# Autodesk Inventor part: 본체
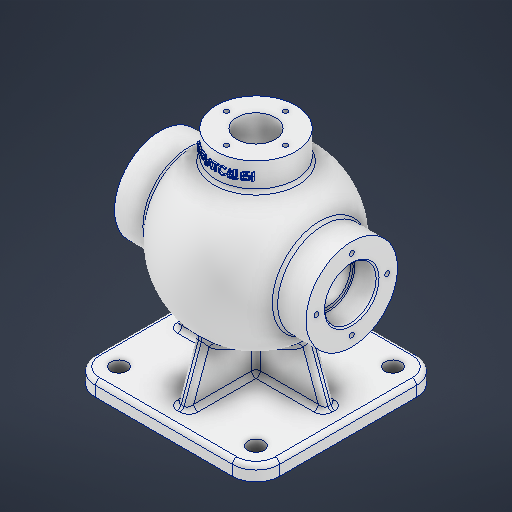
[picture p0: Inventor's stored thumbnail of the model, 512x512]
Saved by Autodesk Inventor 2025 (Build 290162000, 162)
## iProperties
Created: 2025-08
Part Number: 본체
Material: 알루미늄 6061
Document SubType Name: Modeling
Designer: infra005
Density: 2.7 g/cm^3
Appearance: 알루미늄 - 평지
Mass: 1527.05 g
Surface Area: 1174.47 cm^2
Volume: 565.574 cm^3
Author: infra005
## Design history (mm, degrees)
sketch "스케치1"
  geometry: L1 (46.5, 62.5)-(-46.5, 62.5); L2 (-62.5, 46.5)-(-62.5, -46.5); L3 (-46.5, -62.5)-(46.5, -62.5); L4 (62.5, -46.5)-(62.5, 46.5); L5 (62.5, 62.5)-(-62.5, -62.5); L6 (-62.5, 62.5)-(62.5, -62.5); L7 (0, -92.139)-(0, 92.139) reference; A1 r 16 centre (46.5, -46.5) between (46.5, -62.5) and (62.5, -46.5); A2 r 16 centre (-46.5, -46.5) between (-62.5, -46.5) and (-46.5, -62.5); A3 r 16 centre (-46.5, 46.5) between (-46.5, 62.5) and (-62.5, 46.5); A4 r 16 centre (46.5, 46.5) between (62.5, 46.5) and (46.5, 62.5); 1 further point
  constraints: 12 end point, 8 point on circle, 8 point on line, 8 tangent, 4 centre point, 3 equal radius, 2 midpoint, 2 parallel, 1 horizontal, 1 perpendicular
  dimensions: "d0" = 125 distance of L5.end L6.end; "d1" = 125 distance of L6.start L5.end; "d2" = 16 radius of A1
extrude "돌출1" new body sketch "스케치1" distance "d5" = 10; taper "d6" = 0 deg
sketch "스케치3"
  geometry: L1 (0, 159.709)-(0, -26.618) reference; L2 (-79.159, 85)-(102.785, 85); L3 (-115.548, 0)-(139.174, 0) reference; A1 r 54 centre (0, 85) between (0, 139) and (0, 31); 1 further point
  constraints: 4 point on line, 2 end point, 2 point on circle, 1 centre point, 1 horizontal
  dimensions: "d9" = 108 diameter of A1; "d10" = 85 distance between parallel lines of L3 L2
revolve "회전1" sketch "스케치3" stored, may be unused: angle "d11" = 90 deg
sketch "스케치4"
  geometry: L1 (-65, 116)-(0, 116); L2 (0, 116)-(0, 54); L3 (-65, 85)-(-65, 116); L4 (-153.218, 85)-(119.438, 85); L5 (-207.749, 0)-(173.969, 0) reference; L6 (0, 166.8)-(0, -27.8) reference; L7 (-65, 85)-(0, 85); 2 further points
  constraints: 10 end point, 4 point on line, 2 horizontal, 1 parallel, 1 perpendicular
  dimensions: "d13" = 85 distance between parallel lines of L5 L4; "d14" = 31 distance between parallel lines of L4 L1; "d15" = 65 distance of L1.start L1.end
revolve "회전2" sketch "스케치4" stored, may be unused: angle "d16" = 90 deg
node "작업 평면1"
sketch "스케치5"
  geometry: C1 r 27 at (0, 0); 1 further point
  constraints: 1 centre point, 1 coincident
  dimensions: "d18" = 54 diameter of C1
extrude "돌출2" join sketch "스케치5" stored distance "d19" = 10; taper "d20" = 0 deg
sketch "스케치7"
  geometry: L1 (0, 57.838)-(-33.088, 57.838); L2 (-33.088, 57.838)-(-50.5, 10); L3 (-50.5, 10)-(0, 10); L4 (0, 10)-(0, 57.838); L5 (-46.5, 10)-(-62.5, 10) reference; L6 (-62.5, 0)-(-62.5, 10) reference; 2 further points
  constraints: 8 end point, 1 horizontal, 1 midpoint, 1 parallel, 1 perpendicular, 1 point on line
  dimensions: "d24" = 20 deg angle of L4 L2; "d25" = 12 distance from line of L6 L2.end
extrude "돌출3" join sketch "스케치7" stored distance "d26" = 8; taper "d27" = 0 deg
sketch "스케치8"
  geometry: L1 (10, 4)-(10, -4) reference; L2 (10, 0)-(10, -50.5); L3 (10, -46.5)-(10, 46.5) reference; L4 (10, -50.5)-(54.069, -34.46); L5 (54.069, -34.46)-(54.069, 0); L6 (54.069, 0)-(10, 0); L7 (0, -62.5)-(10, -62.5) reference; 2 further points
  constraints: 8 end point, 1 collinear, 1 midpoint, 1 parallel, 1 perpendicular
  dimensions: "d28" = 12 distance from line of L7 L2.end; "d29" = 20 deg angle of L7 L4
extrude "돌출4" join sketch "스케치8" stored distance "d30" = 8; taper "d31" = 0 deg
sketch "스케치9"
  geometry: L1 (-65, 54)-(-65, 116) reference; L2 (-65, 102.5)-(-49, 102.5); L3 (-49, 102.5)-(-49, 100); L4 (-49, 100)-(0, 100); L5 (-88.477, 85)-(100.893, 85); L6 (-126.351, 0)-(138.767, 0) reference; L7 (-65, 102.5)-(-65, 85); L8 (0, 85)-(0, 100); L9 (-65, 85)-(0, 85); 1 further point
  constraints: 14 end point, 3 point on line, 2 horizontal, 2 perpendicular, 1 collinear, 1 midpoint, 1 parallel
  dimensions: "d32" = 85 distance between parallel lines of L6 L5; "d33" = 17.5 distance between parallel lines of L5 L2; "d34" = 15 distance between parallel lines of L5 L4; "d35" = 16 distance between parallel lines of L1 L3
revolve "회전3" sketch "스케치9" stored, may be unused: angle "d36" = 90 deg
sketch "스케치10"
  geometry: L1 (0, 100)-(0, 70) reference; L2 (0, 155.587)-(0, 20.929); L3 (0, 129)-(0, 40.639); A1 r 44 centre (0, 85) between (0, 129) and (0, 41); 4 further points
  constraints: 4 end point, 3 point on line, 2 point on circle, 1 centre point, 1 midpoint, 1 vertical
  dimensions: "d37" = 44 radius of A1
revolve "회전4" sketch "스케치10" stored, may be unused: angle "d38" = 90 deg
sketch "스케치11" dims "d39" = 48
  geometry: L1 (0, 0)-(0, 24); C1 r 31 at (0, 0) reference; 3 further points
  constraints: 2 end point, 1 coincident, 1 vertical, 1 vertical alignment, 3 other
hole "구멍1" sketch "스케치11" at (0, 24) diameter "d40" = 3.242; stored, may be unused: countersink angle "d44" = 90 deg, drill point angle "d46" = 118 deg; dims "d41" = 12, "d42" = 4, "d43" = 2, "d45" = 15
sketch "스케치12"
  geometry: C1 r 13 at (0, 0); 1 further point
  constraints: 1 centre point, 1 coincident
  dimensions: "d50" = 26 diameter of C1
extrude "돌출5" cut sketch "스케치12" stored distance "d51" = 8; taper "d52" = 0 deg
sketch "스케치13"
  geometry: L1 (0, 0)-(0, 20); L2 (0, 87.5)-(0, -87.5) reference; A1 r 20 centre (0, 0) between (0, 20) and (0, 20); 1 further point
  constraints: 2 coincident, 2 end point, 2 point on circle, 1 centre point, 1 point on line
  dimensions: "d53" = 40 diameter of A1
hole "구멍2" sketch "스케치13" at (0, 20) diameter "d54" = 3.242; stored, may be unused: countersink angle "d58" = 90 deg, drill point angle "d60" = 118 deg; dims "d55" = 9, "d56" = 4, "d57" = 2, "d59" = 11
sketch "스케치14"
  geometry: C1 r 5.5 at (-46.5, 46.5); A1 r 16 centre (-46.5, 46.5) between (-46.5, 62.5) and (-62.5, 46.5) reference; 1 further point
  constraints: 1 centre point, 1 concentric
  dimensions: "d64" = 11 diameter of C1
extrude "돌출6" cut sketch "스케치14" distance "d65" = 10; taper "d66" = 0 deg
node "작업 평면2"
sketch "스케치15" dims "d0" = 125, "d1" = 125, "d2" = 16
  geometry: L1 (27, 150)-(-27, 150) reference; L2 (0, 180)-(0, -30) reference; 2 further points
  constraints: 1 point on line, 1 other
  dimensions: "d77" = 9 distance from line of L1 point (0, 141)
feature "엠보싱1" sketch "스케치15" dims "d0" = 125, "d1" = 125, "d2" = 16, "d9" = 108, "d10" = 85, "d78" = 1, "d79" = 0
fillet "모깎기1" dims "d80" = 3
fillet "모깎기2" dims "d81" = 3
chamfer "모따기2" distance "d82" = 1; stored, may be unused: second distance "d83" = 2, angle "d84" = 45 deg
fillet "모깎기3" dims "d85" = 0.6
node "솔리드1"
mirror "미러1"
mirror "미러2"
pattern_circular "원형 패턴1" dims angle "d48" = 360 deg
mirror "미러3"
mirror "미러4"
pattern_circular "원형 패턴2" dims angle "d62" = 360 deg
pattern_linear "직사각형 패턴1" dims "d69" = -93, "d72" = 93
feature "A9D066F2-1C7D-4E18-AEED-F7BC21143FA4" dims "d40" = 3.242, "d41" = 12, "d42" = 4, "d43" = 2, "d44" = 90 deg, "d45" = 15, "d46" = 118 deg
other parameters: "d76" = 27.5
